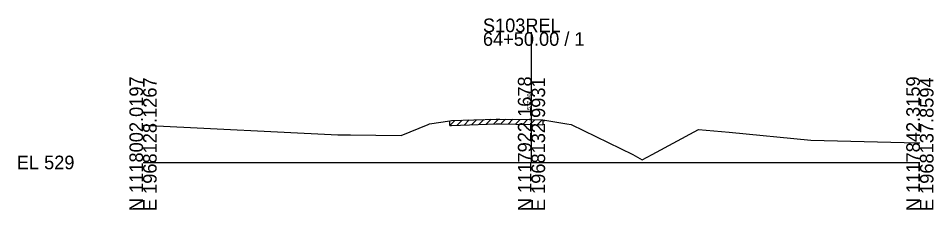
# Model space of a CAD drawing. Extents: x -26 to 163, y -10 to 24518.
# Drawn here: x -25.7 to 162.8, y 12990.3 to 13029.6 of the extents above; entities that cross this region are included whole.
import ezdxf

# ---------------------------------------------------------------- set-up
doc = ezdxf.new("R2010")
doc.units = 0
for name, color, linetype in [('RD_GPK_XS_Cell', 7, 'Continuous'), ('RD_XS_ExGround', 7, 'Continuous'), ('RD_XS_ExPaveRet', 7, 'Continuous'), ('RD_XS_TX_Elev_EX', 7, 'Continuous')]:
    doc.layers.add(name, color=color, linetype=linetype)

msp = doc.modelspace()

# ---------------------------------------------------------------- linework, layer by layer
at = {"layer": 'RD_GPK_XS_Cell'}
for p, q in [((80, 13000), (80, 13026.77)), ((0, 13000), (80, 13000)), ((80, 13000), (160, 13000))]:
    msp.add_line(p, q, dxfattribs=at)
at = {"layer": 'RD_XS_ExGround'}
msp.add_lwpolyline([(0, 13007.67), (1.44, 13007.62), (40.09, 13005.7), (40.49, 13005.68), (42.7, 13005.65), (53.13, 13005.51), (58.72, 13007.79), (59.02, 13007.91), (63.15, 13008.58), (63.55, 13008.6), (72.74, 13008.92), (73.51, 13008.91), (80, 13008.8), (82.34, 13008.76), (87.27, 13007.95), (88.2, 13007.79), (100.88, 13001.62), (102.82, 13000.57), (104.85, 13001.62), (114.4, 13006.8), (120.72, 13006.24), (137.57, 13004.57), (159.5, 13004.04), (160, 13004.03)], dxfattribs=at)
at = {"layer": 'RD_XS_ExPaveRet'}
for p, q in [((67.67, 13007.74), (68.71, 13008.78)), ((69.17, 13007.8), (70.21, 13008.83)), ((70.68, 13007.85), (71.72, 13008.89)), ((72.18, 13007.9), (73.2, 13008.92)), ((73.69, 13007.91), (74.67, 13008.89)), ((75.19, 13007.88), (76.18, 13008.87)), ((76.69, 13007.86), (77.68, 13008.84)), ((78.2, 13007.83), (79.18, 13008.81)), ((79.7, 13007.8), (80.69, 13008.78)), ((81.21, 13007.78), (82.19, 13008.76)), ((82.34, 13008.76), (82.34, 13007.76)), ((63.15, 13007.58), (64.2, 13008.62)), ((63.15, 13007.58), (63.15, 13008.58)), ((63.15, 13007.58), (63.55, 13007.6)), ((63.55, 13007.6), (72.74, 13007.92)), ((64.66, 13007.63), (65.7, 13008.67)), ((66.16, 13007.69), (67.2, 13008.73)), ((72.74, 13007.92), (73.51, 13007.91)), ((73.51, 13007.91), (80, 13007.8)), ((80, 13007.8), (82.34, 13007.76))]:
    msp.add_line(p, q, dxfattribs=at)

# ---------------------------------------------------------------- texts
at = {"layer": 'RD_GPK_XS_Cell'}
for s, p in [('S103REL', (70, 13026.77)), ('64+50.00 / 1', (70, 13023.97)), ('EL 529', (-26, 12998.6))]:
    msp.add_text(s, height=2.8, dxfattribs=at).set_placement(p)
for s, p in [('N 1118002.0197', (0, 12990)), ('E 1968128.1267', (2.8, 12990)), ('N 1117922.1678', (80, 12990)), ('E 1968132.9931', (82.8, 12990)), ('N 1117842.3159', (160, 12990)), ('E 1968137.8594', (162.8, 12990))]:
    msp.add_text(s, height=2.8, rotation=90, dxfattribs=at).set_placement(p)
at = {"layer": 'RD_XS_TX_Elev_EX'}
msp.add_text('537.80', height=0.8, rotation=90, dxfattribs=at).set_placement((79.9, 13010.8))

doc.saveas('drawing.dxf')
